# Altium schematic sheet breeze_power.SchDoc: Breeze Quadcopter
size A4; Author: myyerrol; Organization: Team MicroDynamics; Address1: NWPU; Address2: Xi'an; Address3: Shannxi; Address4: China; Revision: V0.1; SheetNumber: 3; SheetTotal: 5
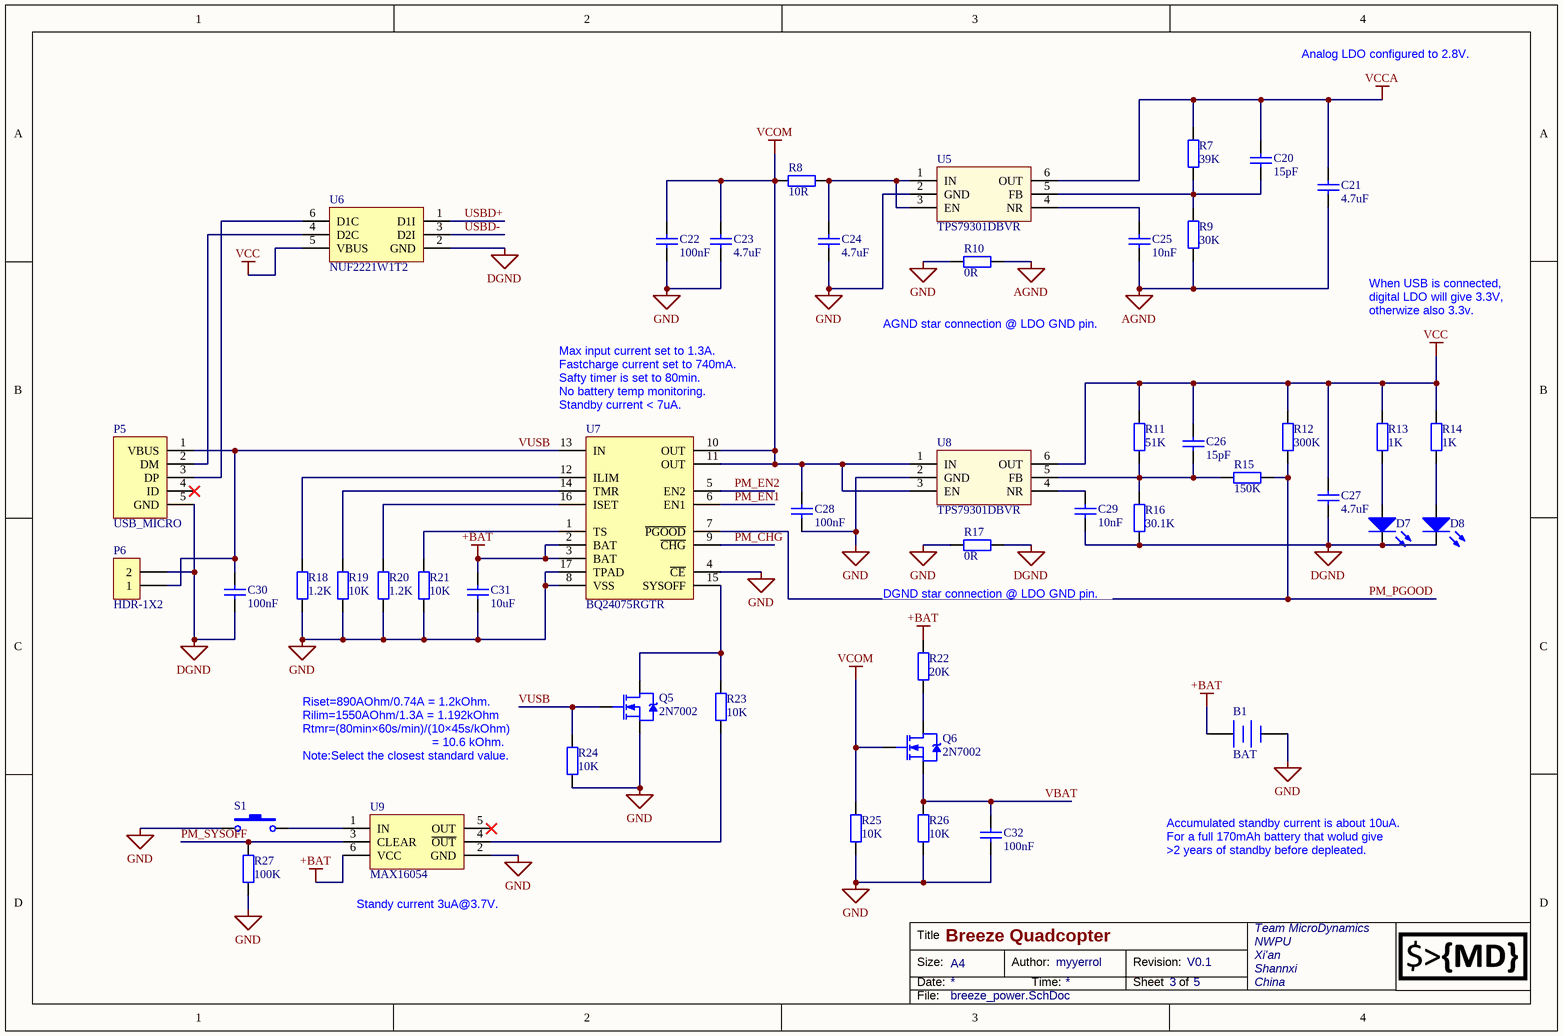
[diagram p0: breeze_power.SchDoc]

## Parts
B1  BAT  [HDR-1X2]
C20  value 15pF  [SMD-0603]  (hidden comment: CAP-0603)
C21  value 4.7uF  [SMD-0603]  (hidden comment: CAP-0603)
C22  value 100nF  [SMD-0603]  (hidden comment: CAP-0603)
C23  value 4.7uF  [SMD-0603]  (hidden comment: CAP-0603)
C24  value 4.7uF  [SMD-0603]  (hidden comment: CAP-0603)
C25  value 10nF  [SMD-0603]  (hidden comment: CAP-0603)
C26  value 15pF  [SMD-0603]  (hidden comment: CAP-0603)
C27  value 4.7uF  [SMD-0603]  (hidden comment: CAP-0603)
C28  value 100nF  [SMD-0603]  (hidden comment: CAP-0603)
C29  value 10nF  [SMD-0603]  (hidden comment: CAP-0603)
C30  value 100nF  [SMD-0603]  (hidden comment: CAP-0603)
C31  value 10uF  [SMD-0603]  (hidden comment: CAP-0603)
C32  value 100nF  [SMD-0603]  (hidden comment: CAP-0603)
D7  LED-0603  [SMD-0603]  (value not drawn)
D8  LED-0603  [SMD-0603]  (value not drawn)
P5  USB_MICRO  [USB_MICRO]
P6  HDR-1X2  [HDR-1X2]
Q5  2N7002  [SOT-23]
Q6  2N7002  [SOT-23]
R7  value 39K  [SMD-0603]  (hidden comment: RES-0603)
R8  value 10R  [SMD-0603]  (hidden comment: RES-0603)
R9  value 30K  [SMD-0603]  (hidden comment: RES-0603)
R10  value 0R  [SMD-0603]  (hidden comment: RES-0603)
R11  value 51K  [SMD-0603]  (hidden comment: RES-0603)
R12  value 300K  [SMD-0603]  (hidden comment: RES-0603)
R13  value 1K  [SMD-0603]  (hidden comment: RES-0603)
R14  value 1K  [SMD-0603]  (hidden comment: RES-0603)
R15  value 150K  [SMD-0603]  (hidden comment: RES-0603)
R16  value 30.1K  [SMD-0603]  (hidden comment: RES-0603)
R17  value 0R  [SMD-0603]  (hidden comment: RES-0603)
R18  value 1.2K  [SMD-0603]  (hidden comment: RES-0603)
R19  value 10K  [SMD-0603]  (hidden comment: RES-0603)
R20  value 1.2K  [SMD-0603]  (hidden comment: RES-0603)
R21  value 10K  [SMD-0603]  (hidden comment: RES-0603)
R22  value 20K  [SMD-0603]  (hidden comment: RES-0603)
R23  value 10K  [SMD-0603]  (hidden comment: RES-0603)
R24  value 10K  [SMD-0603]  (hidden comment: RES-0603)
R25  value 10K  [SMD-0603]  (hidden comment: RES-0603)
R26  value 10K  [SMD-0603]  (hidden comment: RES-0603)
R27  value 100K  [SMD-0603]  (hidden comment: RES-0603)
S1  SKRELGE010  [SKRELGE010]  (value not drawn)
U5  TPS79301DBVR  [SOT-23-6]
U6  NUF2221W1T2  [SOT-363]
U7  BQ24075RGTR  [VQFN-16]
U8  TPS79301DBVR  [SOT-23-6]
U9  MAX16054  [SOT-23-6]

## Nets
+BAT: B1.1(+) C31.1 R22.1 U7.2(BAT) U7.3(BAT) U9.6(VCC)
AGND: C21.2 C25.2 R9.2 R10.2
DGND: C27.2 C29.2 C30.2 D7.2(K) D8.2(K) P5.5(GND) P6.2 R16.2 R17.2 U6.2(GND)
GND: B1.2(-) C22.2 C23.2 C24.2 C28.2 C31.2 C32.2 Q5.2(S) R10.1 R17.1 R18.2 R19.2 R20.2 R21.2 R24.2 R25.2 R26.2 R27.2 S1.1 U5.2(GND) U7.4(~{CE}) U7.8(VSS) U7.17(TPAD) U8.2(GND) U9.2(GND)
VCC: C26.1 C27.1 R11.1 R12.1 R13.1 R14.1 U6.5(VBUS) U8.6(OUT)
VCCA: C20.1 C21.1 R7.1 U5.6(OUT)
VCOM: C22.1 C23.1 C28.1 Q6.1(G) R8.1 R25.1 U7.10(OUT) U7.11(OUT) U8.1(IN) U8.3(EN)
PM_CHG: U7.9(~{CHG})
PM_EN1: U7.6(EN1)
PM_EN2: U7.5(EN2)
PM_PGOOD: R12.2 R15.2 U7.7(~{PGOOD})
PM_SYSOFF: R27.1 U9.3(CLEAR)
USBD+: U6.1(D1I)
USBD-: U6.3(D2I)
VBAT: C32.1 Q6.2(S) R26.1
VUSB: C30.1 P5.1(VBUS) P6.1 Q5.1(G) R24.1 U7.13(IN)
NetC20_2: C20.2 R7.2 R9.1 U5.5(FB)
NetC24_1: C24.1 R8.2 U5.1(IN) U5.3(EN)
NetC25_1: C25.1 U5.4(NR)
NetC26_2: C26.2 R11.2 R15.1 R16.1 U8.5(FB)
NetC29_1: C29.1 U8.4(NR)
NetD7_1: D7.1(A) R13.2
NetD8_1: D8.1(A) R14.2
NetP5_2: P5.2(DM) U6.4(D2C)
NetP5_3: P5.3(DP) U6.6(D1C)
NetQ5_3: Q5.3(D) R23.1 U7.15(SYSOFF)
NetQ6_3: Q6.3(D) R22.2
NetR18_1: R18.1 U7.12(ILIM)
NetR19_1: R19.1 U7.14(TMR)
NetR20_1: R20.1 U7.16(ISET)
NetR21_1: R21.1 U7.1(TS)
NetR23_2: R23.2 U9.4(~{OUT})
NetS1_2: S1.2 U9.1(IN)

Not connected (* = marked no-connect by the designer): P5 4(ID)*; U9 5(OUT)*

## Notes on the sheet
- Analog LDO configured to 2.8V.
- When USB is connected, digital LDO will give 3.3V, otherwize also 3.3v.
- AGND star connection @ LDO GND pin.
- (near U7) Max input current set to 1.3A.
  Fastcharge current set to 740mA.
  Safty timer is set to 80min.
  No battery temp monitoring.
  Standby current < 7uA.
- DGND star connection @ LDO GND pin.
- Riset=890AOhm/0.74A = 1.2kOhm.
  Rilim=1550AOhm/1.3A = 1.192kOhm
  Rtmr=(80min×60s/min)/(10×45s/kOhm)
  = 10.6 kOhm.
  Note:Select the closest standard value.
- Accumulated standby current is about 10uA.
  For a full 170mAh battery that wolud give
  >2 years of standby before depleated.
- (near U9) Standy current 3uA@3.7V.

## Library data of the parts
B1 = BAT: Battery
C20-C32 = CAP-0603: Capacitor
D7 D8 = LED-0603: LED
P5 = USB_MICRO: Micro USB
P6 = HDR-1X2: Header 1X2
Q5 Q6 = 2N7002: N-Channel Enhancement Mode Field Effect Transistor
R7-R27 = RES-0603: Resistor
S1 = SKRELGE010: Switch
U5 U8 = TPS79301DBVR: 200-mA RF Low-Dropout Regulator
U6 = NUF2221W1T2: USB Upstream Terminator  with ESD Protection
U7 = BQ24075RGTR: 1.5-A USB-Friendly Li-Ion Battery Charger and Power-Path Management IC
U9 = MAX16054: On/Off Controller with Debounce and ±15kV ESD Protection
